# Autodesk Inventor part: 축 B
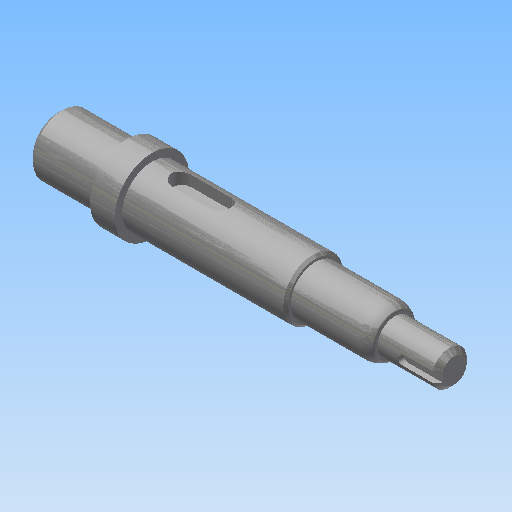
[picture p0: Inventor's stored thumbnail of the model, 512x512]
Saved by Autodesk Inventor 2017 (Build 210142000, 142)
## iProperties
Created: 2020-04
Part Number: 축 B
Material: 강철, 연강
Document SubType Name: Modeling
Designer: mduedu
Density: 1 g/cm^3
Appearance: 강철
Author: mduedu
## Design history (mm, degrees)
sketch "스케치1"
  geometry: L1 (0, 0)-(14, 0); L2 (14, 0)-(14, 6); L3 (14, 6)-(0, 6); L4 (0, 6)-(0, 0); L5 (14, 0)-(19, 0); L6 (19, 0)-(19, 7.5); L7 (19, 7.5)-(14, 7.5); L8 (14, 7.5)-(14, 0); L9 (19, 0)-(52, 0); L10 (52, 0)-(52, 6); L11 (52, 6)-(19, 6); L12 (19, 6)-(19, 0); L13 (52, 0)-(68, 0); L14 (68, 0)-(68, 5); L15 (68, 5)-(52, 5); L16 (52, 5)-(52, 0); L17 (68, 0)-(80, 0); L18 (80, 0)-(80, 3.5); L19 (80, 3.5)-(68, 3.5); L20 (68, 3.5)-(68, 0)
  constraints: 40 end point, 10 parallel, 5 horizontal, 5 perpendicular
  dimensions: "d0" = 80 distance between parallel lines of L18 L4; "d2" = 14 distance of L2.end L3.end; "d3" = 5 distance of L6.end L7.end; "d5" = 7 diameter of L19 L17; "d6" = 10 diameter of L15 L13; "d7" = 12 diameter of L11 L9; "d8" = 12 diameter of L3 L1; "d9" = 15 diameter of L7 L5; "d35" = 16 distance of L14.end L15.end; "d36" = 52 distance between parallel lines of L10 L4
revolve "회전1" sketch "스케치1" stored, may be unused: angle "d11" = 90 deg
sketch "스케치2"
  geometry: L1 (0, 6)-(0, -6) reference; L2 (0, -6)-(-14, -6) reference; L3 (-14, -6)-(-14, -7.5) reference; L4 (-14, -7.5)-(-19, -7.5) reference; L5 (-19, -7.5)-(-19, -6) reference; L6 (-19, -6)-(-52, -6) reference; L7 (-52, -6)-(-52, -5) reference; L8 (-52, -5)-(-68, -5) reference; L9 (-68, -5)-(-68, -3.5) reference; L10 (-68, -3.5)-(-80, -3.5) reference; L11 (-80, -3.5)-(-80, 3.5) reference; L12 (-80, 3.5)-(-68, 3.5) reference; L13 (-68, 3.5)-(-68, 5) reference; L14 (-68, 5)-(-52, 5) reference; L15 (-52, 5)-(-52, 6) reference; L16 (-52, 6)-(-19, 6) reference; L17 (-19, 6)-(-19, 7.5) reference; L18 (-19, 7.5)-(-14, 7.5) reference; L19 (-14, 7.5)-(-14, 6) reference; L20 (-14, 6)-(0, 6) reference; L21 (-80, 3.5)-(-72, 3.5); L22 (-72, 3.5)-(-72, 2.3); L23 (-72, 2.3)-(-80, 2.3); L24 (-80, 2.3)-(-80, 3.5); 1 further point
  constraints: 8 end point, 2 parallel, 1 horizontal, 1 perpendicular
  dimensions: "d37" = 8 distance of L22.end L23.end; "d38" = 1.2 distance of L21.end L22.end
extrude "돌출1" cut sketch "스케치2" stored distance "d14" = 2; taper "d15" = 0 deg
fillet "모깎기1" dims "d16" = 1
sketch "스케치3"
  geometry: L1 (0, -6)-(0, 6) reference; L2 (0, 6)-(14, 6) reference; L3 (14, 6)-(14, 7.5) reference; L4 (14, 7.5)-(19, 7.5) reference; L5 (19, 7.5)-(19, 6) reference; L6 (19, 6)-(52, 6) reference; L7 (52, 6)-(52, 5) reference; L8 (52, 5)-(68, 5) reference; L9 (68, 5)-(68, 3.5) reference; L10 (68, 3.5)-(80, 3.5) reference; L11 (80, 3.5)-(80, -3.5) reference; L12 (80, -3.5)-(68, -3.5) reference; L13 (68, -3.5)-(68, -5) reference; L14 (68, -5)-(52, -5) reference; L15 (52, -5)-(52, -6) reference; L16 (52, -6)-(19, -6) reference; L17 (19, -6)-(19, -7.5) reference; L18 (19, -7.5)-(14, -7.5) reference; L19 (14, -7.5)-(14, -6) reference; L20 (14, -6)-(0, -6) reference; L21 (23, 6)-(35, 6); L22 (35, 6)-(35, 3.5); L23 (35, 3.5)-(23, 3.5); L24 (23, 3.5)-(23, 6); 1 further point
  constraints: 8 end point, 2 parallel, 1 horizontal, 1 perpendicular, 1 point on line
  dimensions: "d17" = 12 distance of L22.end L23.end; "d18" = 2.5 distance of L21.end L22.end; "d19" = 4 distance from line of L24 L4.end
extrude "돌출2" cut sketch "스케치3" stored distance "d20" = 4; taper "d21" = 0 deg
fillet "모깎기2" dims "d22" = 2
chamfer "모따기1" distance "d23" = 1; stored, may be unused: second distance "d24" = 2, angle "d25" = 45 deg
chamfer "모따기2" distance "d26" = 0.5; stored, may be unused: second distance "d27" = 2, angle "d28" = 45 deg
fillet "모깎기3" dims "d29" = 0.3
chamfer "모따기3" distance "d30" = 1.39; stored, may be unused: second distance "d31" = 2, angle "d32" = 30 deg
fillet "모깎기4" dims "d33" = 4, "d34" = 0.5
node "솔리드1"
node "절단 모서리 투영2"
node "절단 모서리 투영3"
